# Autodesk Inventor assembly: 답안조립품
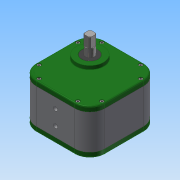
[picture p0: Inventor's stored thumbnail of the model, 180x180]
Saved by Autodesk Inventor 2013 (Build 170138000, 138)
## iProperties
Created: 2017-11
Part Number: 답안조립품
Document SubType Name: Assembly
Designer: Administrator
Mass: 3103.25 g
Surface Area: 2353.72 cm^2
Volume: 855.505 cm^3
Density: 3.62739 g/cm^3
Author: Administrator
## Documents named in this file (11)
- C:\Users\Administrator\Desktop\371108V1010\답안조립품.iam
- C:\Users\Administrator\Desktop\371108V1010\본체.ipt
- C:\Users\Administrator\Desktop\371108V1010\뒤커버.ipt
- C:\Users\Administrator\Desktop\371108V1010\메인축.ipt
- C:\Users\Administrator\Desktop\371108V1010\베어링 608.ipt
- C:\Users\Administrator\Desktop\371108V1010\베어링 6003.ipt
- C:\Users\Administrator\Desktop\371108V1010\볼트 M4.ipt
- C:\Users\Administrator\Desktop\371108V1010\서브축.ipt
- C:\Users\Administrator\Desktop\371108V1010\앞커버.ipt
- C:\Users\Administrator\Desktop\371108V1010\오일실 8 22 7.ipt
- C:\Users\Administrator\Desktop\371108V1010\오일실 17 32 8.ipt
